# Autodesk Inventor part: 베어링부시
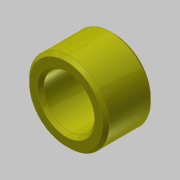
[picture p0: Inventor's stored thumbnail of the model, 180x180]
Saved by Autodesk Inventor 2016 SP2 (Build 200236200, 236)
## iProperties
Created: 2019-03
Part Number: 베어링부시
Material: 강철, 연강
Document SubType Name: Modeling
Designer: mduedu
Density: 1 g/cm^3
Appearance: 노란색
Author: mduedu
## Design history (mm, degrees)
sketch "스케치1"
  geometry: L1 (-7.5, 12.5)-(7.5, 12.5); L2 (7.5, 12.5)-(7.5, 8); L3 (7.5, 8)-(-7.5, 8); L4 (-7.5, 8)-(-7.5, 12.5); L5 (-7.5, 0)-(7.5, 0); 3 further points
  constraints: 10 end point, 2 midpoint, 2 parallel, 2 perpendicular, 2 vertical alignment, 1 coincident, 1 horizontal
  dimensions: "d0" = 16 diameter of L3 L5; "d2" = 25 diameter of L1 L5; "d3" = 15 distance of L1.start L1.end
revolve "회전1" sketch "스케치1" stored, may be unused: angle "d4" = 90 deg
chamfer "모따기1" distance "d5" = 1; stored, may be unused: second distance "d6" = 2, angle "d7" = 45 deg
chamfer "모따기2" distance "d8" = 1; stored, may be unused: second distance "d9" = 2, angle "d10" = 45 deg
node "솔리드1"
